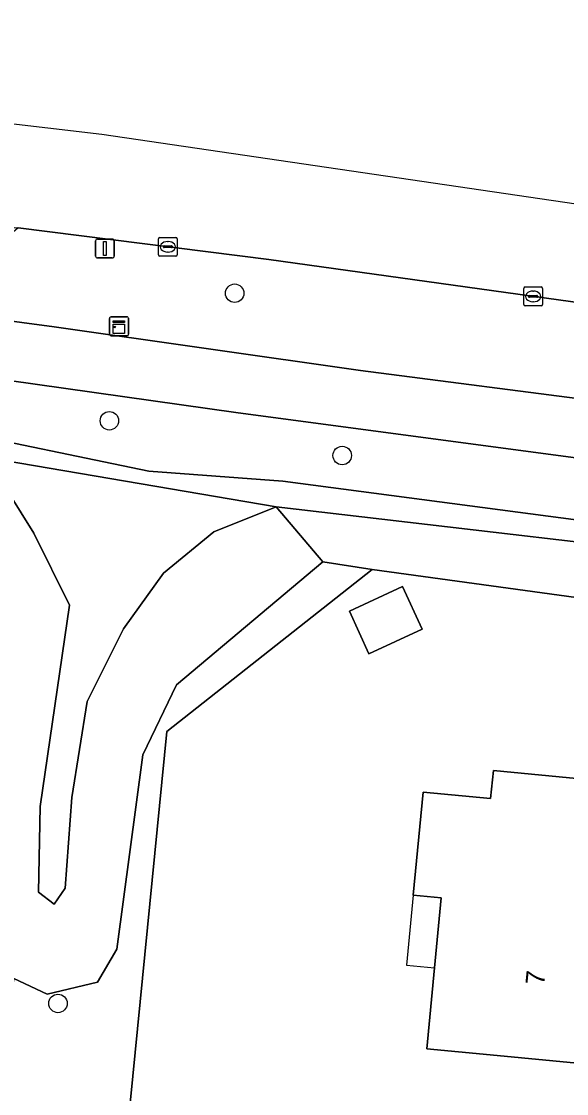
# Model space of a CAD drawing. Extents: x 162156 to 163172, y 378995 to 380779.
# Drawn here: x 162296.7 to 162325.6, y 380702.7 to 380759.6 of the extents above; entities that cross this region are included whole.
import ezdxf

# ---------------------------------------------------------------- set-up
doc = ezdxf.new("R2010")
doc.units = 0
for name, color, linetype in [('IMGEO_Berm_groen', 7, 'Continuous'), ('IMGEO_Boom', 7, 'Continuous'), ('IMGEO_Erf', 7, 'Continuous'), ('IMGEO_Fietspad_open', 7, 'Continuous'), ('IMGEO_Groenvoorziening', 7, 'Continuous'), ('IMGEO_Kast', 7, 'Continuous'), ('IMGEO_Kolk', 7, 'Continuous'), ('IMGEO_Lichtmast', 7, 'Continuous'), ('IMGEO_Pand', 7, 'Continuous'), ('IMGEO_Pand_nummerreeks', 7, 'Continuous'), ('IMGEO_Pand_overbouw', 7, 'Continuous'), ('IMGEO_Rijbaan_lokaal_gesloten', 7, 'Continuous')]:
    doc.layers.add(name, color=color, linetype=linetype)

msp = doc.modelspace()

# ---------------------------------------------------------------- linework, layer by layer
at = {"layer": 'IMGEO_Berm_groen'}
for points in [[(162369.167, 380738.615), (162362.168, 380739.733), (162358.509, 380740.318), (162347.146, 380741.785), (162344.082, 380742.181), (162330.715, 380744.032), (162309.765, 380746.955), (162296.482, 380748.633), (162293.983, 380746.475)], [(162266.518, 380747.721), (162277.284, 380746.222), (162298.393, 380743.379), (162314.638, 380741.08), (162327.765, 380739.371), (162338.555, 380738.008), (162351.072, 380736.25), (162356.297, 380735.58), (162356.856, 380735.509), (162358.655, 380735.278), (162361.722, 380734.839)]]:
    msp.add_lwpolyline(points, dxfattribs=at)
msp.add_lwpolyline([(162308.145, 380738.83), (162266.965, 380744.633), (162266.661, 380742.106), (162269.554, 380741.596), (162281.129, 380739.553), (162292.495, 380737.993), (162303.418, 380735.729), (162310.512, 380735.2), (162337.707, 380731.624), (162337.707, 380734.894)], close=True, dxfattribs=at)
at = {"layer": 'IMGEO_Boom'}
for centre in [(162307.96, 380745.169), (162301.321, 380738.406), (162313.659, 380736.565), (162298.596, 380707.516)]:
    msp.add_circle(centre, 0.489, dxfattribs=at)
at = {"layer": 'IMGEO_Erf'}
msp.add_lwpolyline([(162456.195, 380687.817), (162455.268, 380702.293), (162454.7, 380711.173), (162451.171, 380717.827), (162447.539, 380719.38), (162421.077, 380719.983), (162399.253, 380720.671), (162377.872, 380722.381), (162356.445, 380725.051), (162357.192, 380717.064), (162353.005, 380716.672), (162352.183, 380725.459), (162315.245, 380730.525), (162304.371, 380721.939), (162302.171, 380699.713), (162301.962, 380699.607), (162295.473, 380636.096)], dxfattribs=at)
for points in [[(162315.078, 380726.056), (162314.039, 380728.312), (162316.864, 380729.614), (162317.904, 380727.357)], [(162332.391, 380712.153), (162329.003, 380712.487), (162327.315, 380712.654), (162326.871, 380708.208), (162326.482, 380704.316), (162321.505, 380704.795), (162318.143, 380705.118), (162318.555, 380709.399), (162318.912, 380713.112), (162317.419, 380713.256), (162317.945, 380718.721), (162321.529, 380718.377), (162321.673, 380719.871), (162333.045, 380718.777)]]:
    msp.add_lwpolyline(points, close=True, dxfattribs=at)
at = {"layer": 'IMGEO_Fietspad_open'}
for points in [[(162361.722, 380734.839), (162358.655, 380735.278), (162356.856, 380735.509), (162356.297, 380735.58), (162351.072, 380736.25), (162338.555, 380738.008), (162327.765, 380739.371), (162314.638, 380741.08), (162298.393, 380743.379), (162277.284, 380746.222), (162266.518, 380747.721), (162262.338, 380748.306)], [(162253.923, 380746.456), (162256.265, 380746.136), (162261.032, 380745.421), (162266.965, 380744.633), (162308.145, 380738.83), (162337.707, 380734.894), (162353.401, 380732.804), (162374.742, 380730.259)]]:
    msp.add_lwpolyline(points, dxfattribs=at)
at = {"layer": 'IMGEO_Groenvoorziening'}
for points in [[(162337.707, 380731.624), (162310.512, 380735.2), (162303.418, 380735.729), (162292.495, 380737.993), (162281.129, 380739.553), (162269.554, 380741.596), (162274.252, 380739.465), (162292.506, 380736.854), (162310.16, 380733.836), (162337.707, 380730.635)], [(162292.506, 380736.854), (162295.365, 380735.548), (162297.325, 380732.44), (162299.2, 380728.637), (162297.647, 380717.959), (162297.561, 380713.411), (162298.386, 380712.775), (162298.98, 380713.627), (162299.333, 380718.442), (162300.137, 380723.528), (162302.063, 380727.381), (162304.186, 380730.333), (162306.85, 380732.511), (162310.16, 380733.836)]]:
    msp.add_lwpolyline(points, close=True, dxfattribs=at)
for points in [[(162296.259, 380708.847), (162298.025, 380708.015), (162300.695, 380708.651), (162301.711, 380710.396), (162303.091, 380720.691), (162304.88, 380724.402), (162312.639, 380730.931), (162310.16, 380733.836), (162306.85, 380732.511), (162304.186, 380730.333), (162302.063, 380727.381), (162300.137, 380723.528), (162299.333, 380718.442), (162298.98, 380713.627), (162298.386, 380712.775), (162297.561, 380713.411), (162297.647, 380717.959), (162299.2, 380728.637), (162297.325, 380732.44), (162295.365, 380735.548)], [(162337.707, 380730.635), (162310.16, 380733.836), (162312.639, 380730.931), (162315.245, 380730.525), (162352.183, 380725.459)], [(162301.962, 380699.607), (162302.171, 380699.713), (162304.371, 380721.939), (162315.245, 380730.525), (162312.639, 380730.931), (162304.88, 380724.402), (162303.091, 380720.691), (162301.711, 380710.396), (162300.695, 380708.651), (162298.025, 380708.015), (162296.259, 380708.847), (162296.214, 380708.615), (162295.923, 380707.125), (162290.44, 380679.036), (162288.388, 380677.953), (162286.154, 380652.817)]]:
    msp.add_lwpolyline(points, dxfattribs=at)
at = {"layer": 'IMGEO_Kast'}
for p, q in [((162301.33, 380742.989), (162301.33, 380743.83)), ((162301.33, 380743.83), (162301.33, 380742.989)), ((162301.405, 380743.914), (162302.246, 380743.914)), ((162302.246, 380743.914), (162301.405, 380743.914)), ((162302.33, 380743.839), (162302.33, 380742.998)), ((162302.33, 380742.998), (162302.33, 380743.839)), ((162302.255, 380742.914), (162301.414, 380742.914)), ((162301.414, 380742.914), (162302.255, 380742.914))]:
    msp.add_line(p, q, dxfattribs=at)
for points in [[(162301.525, 380743.704), (162302.125, 380743.704), (162302.125, 380743.619), (162301.525, 380743.619), (162301.525, 380743.704)], [(162301.525, 380743.529), (162302.125, 380743.529), (162302.125, 380743.04), (162301.525, 380743.04), (162301.525, 380743.529)]]:
    msp.add_lwpolyline(points, dxfattribs=at)
msp.add_circle((162301.609, 380743.378), 0.0377, dxfattribs=at)
for centre, start, end in [((162301.408, 380743.836), 92.4484, 184.2845), ((162301.408, 380743.836), 92.4484, 184.2845), ((162302.252, 380743.836), 2.4484, 94.2845), ((162302.252, 380743.836), 2.4484, 94.2845), ((162301.408, 380742.992), 182.4484, 274.2845), ((162301.408, 380742.992), 182.4484, 274.2845), ((162302.252, 380742.992), 272.4484, 4.2845), ((162302.252, 380742.992), 272.4484, 4.2845)]:
    msp.add_arc(centre, 0.0779, start, end, dxfattribs=at)
at = {"layer": 'IMGEO_Kolk'}
for p, q in [((162303.92, 380747.204), (162303.92, 380748.056)), ((162303.995, 380748.13), (162304.847, 380748.13)), ((162304.921, 380748.056), (162304.921, 380747.204)), ((162304.179, 380747.624), (162304.179, 380747.636)), ((162304.617, 380747.587), (162304.219, 380747.587)), ((162304.222, 380747.673), (162304.62, 380747.673)), ((162304.408, 380747.91), (162304.433, 380747.91)), ((162304.663, 380747.636), (162304.663, 380747.624)), ((162304.847, 380747.13), (162303.995, 380747.13)), ((162304.431, 380747.35), (162304.406, 380747.35)), ((162323.28, 380744.573), (162323.28, 380745.425)), ((162323.355, 380745.499), (162324.207, 380745.499)), ((162323.768, 380745.279), (162323.793, 380745.279)), ((162324.281, 380745.425), (162324.281, 380744.573)), ((162323.539, 380744.993), (162323.539, 380745.005)), ((162323.977, 380744.956), (162323.579, 380744.956)), ((162323.582, 380745.042), (162323.98, 380745.042)), ((162323.791, 380744.719), (162323.766, 380744.719)), ((162324.023, 380745.005), (162324.023, 380744.993)), ((162324.207, 380744.499), (162323.355, 380744.499))]:
    msp.add_line(p, q, dxfattribs=at)
for points in [[(162303.92, 380747.204), (162303.92, 380748.056)], [(162303.995, 380748.13), (162304.847, 380748.13)], [(162304.921, 380748.056), (162304.921, 380747.204)], [(162304.847, 380747.13), (162303.995, 380747.13)], [(162323.28, 380744.573), (162323.28, 380745.425)], [(162323.355, 380745.499), (162324.207, 380745.499)], [(162324.281, 380745.425), (162324.281, 380744.573)], [(162324.207, 380744.499), (162323.355, 380744.499)]]:
    msp.add_lwpolyline(points, dxfattribs=at)
for centre, radius, start, end in [((162303.997, 380748.054), 0.0765, 91.552, 178.448), ((162303.997, 380748.054), 0.0765, 91.552, 178.448), ((162304.845, 380748.054), 0.0765, 1.552, 88.448), ((162304.845, 380748.054), 0.0765, 1.552, 88.448), ((162304.219, 380747.633), 0.0403, 85.8775, 175.7526), ((162304.216, 380747.623), 0.0366, 178.938, 274.7102), ((162304.62, 380747.63), 0.043, 264.8664, 352.4533), ((162304.624, 380747.635), 0.0386, 1.7309, 96.639), ((162303.997, 380747.206), 0.0765, 181.552, 268.448), ((162303.997, 380747.206), 0.0765, 181.552, 268.448), ((162304.845, 380747.206), 0.0765, 271.552, 358.448), ((162304.845, 380747.206), 0.0765, 271.552, 358.448), ((162323.357, 380745.423), 0.0765, 91.552, 178.448), ((162323.357, 380745.423), 0.0765, 91.552, 178.448), ((162324.205, 380745.423), 0.0765, 1.552, 88.448), ((162324.205, 380745.423), 0.0765, 1.552, 88.448), ((162323.579, 380745.002), 0.0403, 85.8775, 175.7526), ((162323.576, 380744.992), 0.0366, 178.938, 274.7102), ((162323.98, 380744.999), 0.043, 264.8664, 352.4533), ((162323.984, 380745.004), 0.0386, 1.7309, 96.639), ((162323.357, 380744.575), 0.0765, 181.552, 268.448), ((162323.357, 380744.575), 0.0765, 181.552, 268.448), ((162324.205, 380744.575), 0.0765, 271.552, 358.448), ((162324.205, 380744.575), 0.0765, 271.552, 358.448)]:
    msp.add_arc(centre, radius, start, end, dxfattribs=at)
for centre, major_axis, ratio, start_param, end_param in [((162304.407, 380747.63), (-0.387, 0.002), 0.722429, 4.712389, 7.853982), ((162304.432, 380747.63), (-0.39, 0.002), 0.717154, 1.570796, 4.712389), ((162323.767, 380744.999), (-0.387, 0.002), 0.722429, 4.712389, 7.853982), ((162323.792, 380744.999), (-0.39, 0.002), 0.717154, 1.570796, 4.712389)]:
    msp.add_ellipse(centre, major_axis=major_axis, ratio=ratio, start_param=start_param, end_param=end_param, dxfattribs=at)
at = {"layer": 'IMGEO_Lichtmast'}
for p, q in [((162300.686, 380748.041), (162301.476, 380748.041)), ((162301.476, 380748.041), (162300.686, 380748.041)), ((162300.586, 380747.141), (162300.586, 380747.941)), ((162300.586, 380747.941), (162300.586, 380747.141)), ((162301.576, 380747.941), (162301.576, 380747.141)), ((162301.576, 380747.141), (162301.576, 380747.941)), ((162301.476, 380747.041), (162300.686, 380747.041)), ((162300.686, 380747.041), (162301.476, 380747.041))]:
    msp.add_line(p, q, dxfattribs=at)
msp.add_lwpolyline([(162301.006, 380747.916), (162301.156, 380747.916), (162301.156, 380747.166), (162301.006, 380747.166), (162301.006, 380747.916)], dxfattribs=at)
for centre, start, end in [((162300.686, 380747.941), 90, 180), ((162300.686, 380747.941), 90, 180), ((162301.476, 380747.941), 0, 90), ((162301.476, 380747.941), 360, 90), ((162300.686, 380747.141), 180, 270), ((162300.686, 380747.141), 180, 270), ((162301.476, 380747.141), 270, 0), ((162301.476, 380747.141), 270, 0)]:
    msp.add_arc(centre, 0.1, start, end, dxfattribs=at)
at = {"layer": 'IMGEO_Pand'}
for points in [[(162314.039, 380728.312), (162315.078, 380726.056), (162317.904, 380727.357), (162316.864, 380729.614)], [(162333.045, 380718.777), (162321.673, 380719.871), (162321.529, 380718.377), (162317.945, 380718.721), (162317.419, 380713.256), (162318.912, 380713.112), (162318.555, 380709.399), (162318.143, 380705.118), (162321.505, 380704.795), (162326.482, 380704.316), (162326.871, 380708.208), (162327.315, 380712.654), (162329.003, 380712.487), (162332.391, 380712.153)]]:
    msp.add_lwpolyline(points, close=True, dxfattribs=at)
at = {"layer": 'IMGEO_Pand_overbouw'}
msp.add_lwpolyline([(162318.912, 380713.112), (162317.419, 380713.256), (162317.062, 380709.543), (162318.555, 380709.399)], close=True, dxfattribs=at)
at = {"layer": 'IMGEO_Rijbaan_lokaal_gesloten'}
for points in [[(162392.576, 380743.795), (162389.847, 380744), (162365.037, 380744.169), (162300.915, 380753.574), (162249.838, 380759.576), (162249.309, 380754.329)], [(162262.89, 380753.26), (162263.002, 380753.245), (162267.278, 380752.687), (162268.339, 380752.513), (162296.273, 380748.659), (162296.482, 380748.633), (162309.765, 380746.955), (162330.715, 380744.032), (162344.082, 380742.181), (162347.146, 380741.785), (162358.509, 380740.318), (162362.168, 380739.733), (162369.167, 380738.615), (162375.561, 380737.276)]]:
    msp.add_lwpolyline(points, dxfattribs=at)

# ---------------------------------------------------------------- texts
at = {"layer": 'IMGEO_Pand_nummerreeks'}
msp.add_text('7', height=1, rotation=84.2936, dxfattribs=at).set_placement((162324.363, 380708.461))

doc.saveas('drawing.dxf')
